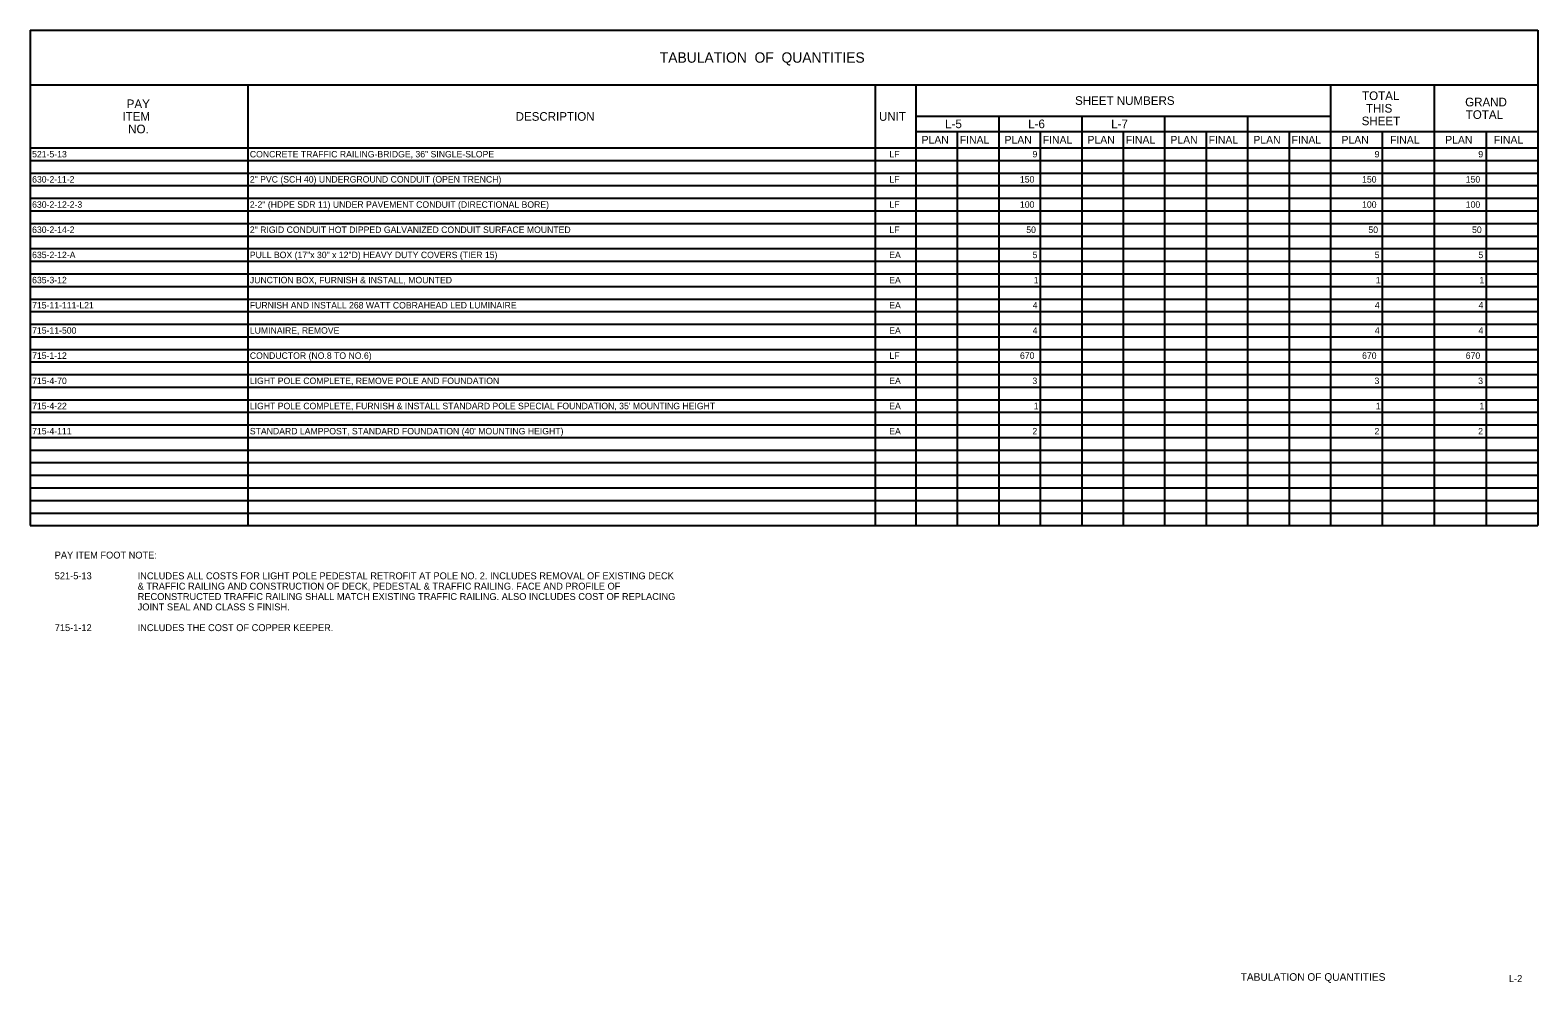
# Model space of a CAD drawing. Extents: x 0.1 to 15.4, y -0.2 to 9.4.
import ezdxf

# ---------------------------------------------------------------- set-up
doc = ezdxf.new("R2010")
doc.units = 0
for name, color, linetype in [('NonPlottingEle_dp', 7, 'Continuous'), ('SumBoxBorder_dp', 7, 'Continuous'), ('SumBoxLines_dp', 7, 'Continuous'), ('SumBoxLinesMin_dp', 7, 'Continuous'), ('TextLabel', 7, 'Continuous'), ('TextNotes', 7, 'Continuous')]:
    doc.layers.add(name, color=color, linetype=linetype)

msp = doc.modelspace()

# ---------------------------------------------------------------- linework, layer by layer
at = {"layer": 'SumBoxBorder_dp'}
for p, q in [((0.097, 9.428), (15.367, 9.428)), ((0.097, 9.428), (0.097, 4.41)), ((15.367, 9.428), (15.367, 4.41)), ((0.097, 8.873), (15.367, 8.873)), ((0.097, 8.873), (15.367, 8.873)), ((0.097, 4.41), (15.367, 4.41))]:
    msp.add_line(p, q, dxfattribs=at)
at = {"layer": 'SumBoxLines_dp'}
for p, q in [((2.302, 8.873), (2.302, 4.41)), ((2.302, 8.873), (2.302, 4.41)), ((8.655, 8.873), (8.655, 4.41)), ((8.655, 8.873), (8.655, 4.41)), ((9.067, 8.873), (9.067, 8.4)), ((9.067, 8.873), (9.067, 4.41)), ((13.267, 8.873), (13.267, 4.41)), ((14.317, 8.873), (14.317, 4.41)), ((9.067, 8.558), (13.267, 8.558)), ((9.067, 8.558), (13.267, 8.558)), ((9.907, 8.558), (9.907, 4.41)), ((9.907, 8.558), (9.907, 4.41)), ((10.747, 8.558), (10.747, 4.41)), ((10.747, 8.558), (10.747, 8.4)), ((11.587, 8.558), (11.587, 4.41)), ((11.587, 8.558), (11.587, 8.4)), ((12.427, 8.558), (12.427, 4.41)), ((12.427, 8.558), (12.427, 4.41)), ((13.267, 8.558), (13.267, 4.41)), ((9.067, 8.4), (15.367, 8.4)), ((13.267, 8.4), (15.367, 8.4)), ((14.317, 8.4), (14.317, 4.41)), ((0.097, 8.235), (15.367, 8.235)), ((0.097, 8.235), (13.267, 8.235)), ((9.067, 8.235), (9.067, 4.41)), ((10.747, 8.235), (10.747, 4.41)), ((11.587, 8.235), (11.587, 4.41)), ((13.792, 8.235), (14.317, 8.235)), ((14.842, 8.235), (15.367, 8.235)), ((12.427, 7.98), (13.267, 7.98)), ((13.792, 7.98), (14.317, 7.98)), ((14.842, 7.98), (15.367, 7.98))]:
    msp.add_line(p, q, dxfattribs=at)
at = {"layer": 'SumBoxLinesMin_dp'}
for p, q in [((9.487, 8.4), (9.487, 4.41)), ((9.487, 8.4), (9.487, 4.41)), ((10.327, 8.4), (10.327, 4.41)), ((10.327, 8.4), (10.327, 4.41)), ((10.747, 8.4), (10.747, 8.235)), ((11.167, 8.4), (11.167, 4.41)), ((11.167, 8.4), (11.167, 4.41)), ((11.587, 8.4), (11.587, 8.235)), ((12.007, 8.4), (12.007, 4.41)), ((12.007, 8.4), (12.007, 4.41)), ((12.847, 8.4), (12.847, 4.41)), ((12.847, 8.4), (12.847, 4.41)), ((13.792, 8.4), (13.792, 4.41)), ((13.792, 8.4), (13.792, 4.41)), ((14.842, 8.4), (14.842, 4.41)), ((14.842, 8.4), (14.842, 4.41)), ((0.097, 8.108), (15.367, 8.108)), ((0.097, 8.108), (15.367, 8.108)), ((13.267, 8.235), (13.792, 8.235)), ((14.317, 8.235), (14.842, 8.235)), ((0.097, 7.98), (12.427, 7.98)), ((9.067, 7.98), (15.367, 7.98)), ((13.267, 7.98), (13.792, 7.98)), ((14.317, 7.98), (14.842, 7.98)), ((0.097, 7.853), (15.367, 7.853)), ((0.097, 7.853), (15.367, 7.853)), ((0.097, 7.725), (15.367, 7.725)), ((0.097, 7.725), (15.367, 7.725)), ((0.097, 7.598), (15.367, 7.598)), ((0.097, 7.598), (15.367, 7.598)), ((0.097, 7.47), (15.367, 7.47)), ((0.097, 7.47), (15.367, 7.47)), ((0.097, 7.343), (15.367, 7.343)), ((0.097, 7.343), (15.367, 7.343)), ((0.097, 7.215), (15.367, 7.215)), ((0.097, 7.215), (15.367, 7.215)), ((0.097, 7.088), (15.367, 7.088)), ((0.097, 7.088), (15.367, 7.088)), ((0.097, 6.96), (15.367, 6.96)), ((0.097, 6.96), (15.367, 6.96)), ((0.097, 6.833), (15.367, 6.833)), ((0.097, 6.833), (15.367, 6.833)), ((0.097, 6.705), (15.367, 6.705)), ((0.097, 6.705), (15.367, 6.705)), ((0.097, 6.578), (15.367, 6.578)), ((0.097, 6.578), (15.367, 6.578)), ((0.097, 6.45), (15.367, 6.45)), ((0.097, 6.45), (15.367, 6.45)), ((0.097, 6.323), (15.367, 6.323)), ((0.097, 6.323), (15.367, 6.323)), ((0.097, 6.195), (15.367, 6.195)), ((0.097, 6.195), (15.367, 6.195)), ((0.097, 6.068), (15.367, 6.068)), ((0.097, 6.068), (15.367, 6.068)), ((0.097, 5.94), (15.367, 5.94)), ((0.097, 5.94), (15.367, 5.94)), ((0.097, 5.813), (15.367, 5.813)), ((0.097, 5.813), (15.367, 5.813)), ((0.097, 5.685), (15.367, 5.685)), ((0.097, 5.685), (15.367, 5.685)), ((0.097, 5.558), (15.367, 5.558)), ((0.097, 5.558), (15.367, 5.558)), ((0.097, 5.43), (15.367, 5.43)), ((0.097, 5.43), (15.367, 5.43)), ((0.097, 5.303), (15.367, 5.303)), ((0.097, 5.303), (15.367, 5.303)), ((0.097, 5.175), (15.367, 5.175)), ((0.097, 5.175), (15.367, 5.175)), ((0.097, 5.048), (15.367, 5.048)), ((0.097, 5.048), (15.367, 5.048)), ((0.097, 4.92), (15.367, 4.92)), ((0.097, 4.92), (15.367, 4.92)), ((0.097, 4.793), (15.367, 4.793)), ((0.097, 4.793), (15.367, 4.793)), ((0.097, 4.665), (15.367, 4.665)), ((0.097, 4.665), (15.367, 4.665)), ((0.097, 4.538), (15.367, 4.538)), ((0.097, 4.538), (15.367, 4.538))]:
    msp.add_line(p, q, dxfattribs=at)

# ---------------------------------------------------------------- texts
at = {"layer": 'NonPlottingEle_dp'}
msp.add_text('L-2', height=0.07, dxfattribs=at).set_placement((15.074, -0.211))
at = {"layer": 'TextLabel'}
for s, height, p in [('TABULATION  OF  QUANTITIES', 0.105, (6.474, 9.098)), ('PAY', 0.0875, (1.075, 8.638)), ('SHEET NUMBERS', 0.0875, (10.68, 8.671)), ('TOTAL', 0.0875, (13.587, 8.72)), ('GRAND', 0.0875, (14.631, 8.656)), ('ITEM', 0.0875, (1.032, 8.51)), ('DESCRIPTION', 0.0875, (5.014, 8.51)), ('UNIT', 0.0875, (8.694, 8.51)), ('SHEET', 0.0875, (13.583, 8.465)), ('THIS', 0.0875, (13.626, 8.593)), ('TOTAL', 0.0875, (14.637, 8.529)), ('NO.', 0.0875, (1.09, 8.383)), ('L-5', 0.0875, (9.364, 8.435)), ('L-6', 0.0875, (10.205, 8.435)), ('L-7', 0.0875, (11.046, 8.435)), ('PLAN', 0.0788, (9.126, 8.278)), ('FINAL', 0.0788, (9.513, 8.278)), ('PLAN', 0.0788, (9.966, 8.278)), ('FINAL', 0.0788, (10.353, 8.278)), ('PLAN', 0.0788, (10.806, 8.278)), ('FINAL', 0.0788, (11.193, 8.278)), ('PLAN', 0.0788, (11.646, 8.278)), ('FINAL', 0.0788, (12.033, 8.278)), ('PLAN', 0.0788, (12.486, 8.278)), ('FINAL', 0.0788, (12.873, 8.278)), ('PLAN', 0.0788, (13.379, 8.278)), ('FINAL', 0.0788, (13.87, 8.278)), ('PLAN', 0.0788, (14.429, 8.278)), ('FINAL', 0.0788, (14.92, 8.278)), ('521-5-13', 0.0656, (0.117, 8.139)), ('CONCRETE TRAFFIC RAILING-BRIDGE, 36" SINGLE-SLOPE', 0.06563, (2.322, 8.139)), ('LF', 0.0656, (8.8, 8.139)), ('9', 0.0656, (10.249, 8.139)), ('9', 0.0656, (13.714, 8.139)), ('9', 0.0656, (14.764, 8.139)), ('630-2-11-2', 0.0656, (0.117, 7.884)), ('2" PVC (SCH 40) UNDERGROUND CONDUIT (OPEN TRENCH)', 0.06563, (2.322, 7.884)), ('LF', 0.0656, (8.8, 7.884)), ('150', 0.0656, (10.122, 7.884)), ('150', 0.0656, (13.587, 7.884)), ('150', 0.0656, (14.637, 7.884)), ('630-2-12-2-3', 0.06563, (0.117, 7.629)), ('2-2" (HDPE SDR 11) UNDER PAVEMENT CONDUIT (DIRECTIONAL BORE)', 0.06563, (2.322, 7.629)), ('LF', 0.0656, (8.8, 7.629)), ('100', 0.0656, (10.122, 7.629)), ('100', 0.0656, (13.587, 7.629)), ('100', 0.0656, (14.637, 7.629)), ('630-2-14-2', 0.0656, (0.117, 7.374)), ('2" RIGID CONDUIT HOT DIPPED GALVANIZED CONDUIT SURFACE MOUNTED', 0.06563, (2.322, 7.374)), ('LF', 0.0656, (8.8, 7.374)), ('50', 0.0656, (10.186, 7.374)), ('50', 0.0656, (13.651, 7.374)), ('50', 0.0656, (14.701, 7.374)), ('635-2-12-A', 0.0656, (0.117, 7.119)), ('PULL BOX (17"x 30" x 12"D) HEAVY DUTY COVERS (TIER 15)', 0.06563, (2.322, 7.119)), ('EA', 0.0656, (8.798, 7.119)), ('5', 0.0656, (10.25, 7.119)), ('5', 0.0656, (13.715, 7.119)), ('5', 0.0656, (14.765, 7.119)), ('635-3-12', 0.0656, (0.117, 6.864)), ('JUNCTION BOX, FURNISH & INSTALL, MOUNTED', 0.06563, (2.322, 6.864)), ('EA', 0.0656, (8.798, 6.864)), ('1', 0.0656, (10.261, 6.864)), ('1', 0.0656, (13.726, 6.864)), ('1', 0.0656, (14.776, 6.864)), ('715-11-111-L21', 0.06563, (0.117, 6.609)), ('FURNISH AND INSTALL 268 WATT COBRAHEAD LED LUMINAIRE', 0.06563, (2.322, 6.609)), ('EA', 0.0656, (8.798, 6.609)), ('4', 0.0656, (10.251, 6.609)), ('4', 0.0656, (13.716, 6.609)), ('4', 0.0656, (14.766, 6.609)), ('715-11-500', 0.0656, (0.117, 6.354)), ('LUMINAIRE, REMOVE', 0.06563, (2.322, 6.354)), ('EA', 0.0656, (8.798, 6.354)), ('4', 0.0656, (10.251, 6.354)), ('4', 0.0656, (13.716, 6.354)), ('4', 0.0656, (14.766, 6.354)), ('715-1-12', 0.0656, (0.117, 6.099)), ('CONDUCTOR (NO.8 TO NO.6)', 0.06563, (2.322, 6.099)), ('LF', 0.0656, (8.8, 6.099)), ('670', 0.0656, (10.122, 6.099)), ('670', 0.0656, (13.587, 6.099)), ('670', 0.0656, (14.637, 6.099)), ('715-4-70', 0.0656, (0.117, 5.844)), ('LIGHT POLE COMPLETE, REMOVE POLE AND FOUNDATION', 0.06563, (2.322, 5.844)), ('EA', 0.0656, (8.798, 5.844)), ('3', 0.0656, (10.248, 5.844)), ('3', 0.0656, (13.713, 5.844)), ('3', 0.0656, (14.763, 5.844)), ('715-4-22', 0.0656, (0.117, 5.589)), ("LIGHT POLE COMPLETE, FURNISH & INSTALL STANDARD POLE SPECIAL FOUNDATION, 35' MOUNTING HEIGHT", 0.06563, (2.322, 5.589)), ('EA', 0.0656, (8.798, 5.589)), ('1', 0.0656, (10.261, 5.589)), ('1', 0.0656, (13.726, 5.589)), ('1', 0.0656, (14.776, 5.589)), ('715-4-111', 0.0656, (0.117, 5.334)), ("STANDARD LAMPPOST, STANDARD FOUNDATION (40' MOUNTING HEIGHT)", 0.06563, (2.322, 5.334)), ('EA', 0.0656, (8.798, 5.334)), ('2', 0.0656, (10.248, 5.334)), ('2', 0.0656, (13.713, 5.334)), ('2', 0.0656, (14.763, 5.334)), ('TABULATION OF QUANTITIES', 0.07709, (12.357, -0.199))]:
    msp.add_text(s, height=height, dxfattribs=at).set_placement(p)
at = {"layer": 'TextNotes'}
for s, p in [('PAY ITEM FOOT NOTE:', (0.346, 4.077)), ('521-5-13', (0.346, 3.867)), ('& TRAFFIC RAILING AND CONSTRUCTION OF DECK, PEDESTAL & TRAFFIC RAILING. FACE AND PROFILE OF ', (1.186, 3.762)), ('INCLUDES ALL COSTS FOR LIGHT POLE PEDESTAL RETROFIT AT POLE NO. 2. INCLUDES REMOVAL OF EXISTING DECK', (1.186, 3.867)), ('RECONSTRUCTED TRAFFIC RAILING SHALL MATCH EXISTING TRAFFIC RAILING. ALSO INCLUDES COST OF REPLACING ', (1.186, 3.657)), ('JOINT SEAL AND CLASS S FINISH.', (1.186, 3.552)), ('715-1-12', (0.346, 3.342)), ('INCLUDES THE COST OF COPPER KEEPER. ', (1.186, 3.342))]:
    msp.add_text(s, height=0.07, dxfattribs=at).set_placement(p)

doc.saveas('drawing.dxf')
